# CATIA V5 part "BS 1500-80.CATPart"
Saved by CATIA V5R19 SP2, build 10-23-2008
Part number: BS 1500-80
Bounding box of the stored display mesh (mm): x -31.459 to 31.459, y -31.459 to 31.459, z 0 to 204
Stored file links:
  C:\Users\Bora\Desktop\3D Katı model\BS serisi\BS 1500\BS 1500-80.CATPart
  C:\Program Files\Dassault Systemes\B19\intel_a\reffiles\standard\MetricThickPitch.txt
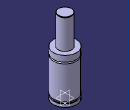
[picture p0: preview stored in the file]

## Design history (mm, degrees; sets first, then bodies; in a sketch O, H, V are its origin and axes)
Body1 (main body)
  Sketch1 on yz-plane, origin (0, 0, 0), H (0, 1, 0), V (0, 0, 1)
    point P1 (31.5, 107)
    point P2 (31.5, 103)
    point P3 (31.5, 107)
    point P7 (18, 203)
    point P9 (18, 203)
    point P14 (31.5, 103)
    arc A1 centre (31.5, 105) radius 2 from (31.5, 107) to (31.5, 103) ccw
    line L1 (31.5, 107) -> (31.5, 123)
    line L2 (31.5, 0) -> (31.5, 8)
    arc A2 centre (17, 203) radius 1 from (18, 203) to (17, 204) ccw
    line L3 (18, 203) -> (18, 123)
    line L4 (29, 13) -> (29, 8)
    line L5 (31.5, 13) -> (31.5, 103)
    line L6 (17, 204) -> (0, 204)
    point P15 (0, 204)
    line L7 (18, 123) -> (31.5, 123)
    line L8 (0, 0) -> (31.5, 0)
    line L9 (29, 13) -> (31.5, 13)
    line L10 (29, 8) -> (31.5, 8)
    coincidence: P15 V, P1 P3, P2 P14, P7 P9
    tangency: L6 A2
    horizontal: L7 H, L8 H, L9 H, L10 H
  Shaft1: profile Sketch1, axis Sketch1.V, angle 360
  Sketch2 on face of Shaft1 from Sketch1.L8, origin (0, 0, 0), H (1, 0, 0), V (0, -1, 0)
    point P1 (10, 0)
    distance P1 V = 10
  Hole1: placed by Sketch2, at (10, 0, 0) direction (0, 0, 1), diameter 6.647, depth 5, threaded "M8", thread diameter 8, thread depth 5, pitch 1.25
  CircPattern1: of Hole1, instances 2, angular step 180, axis from xy-plane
